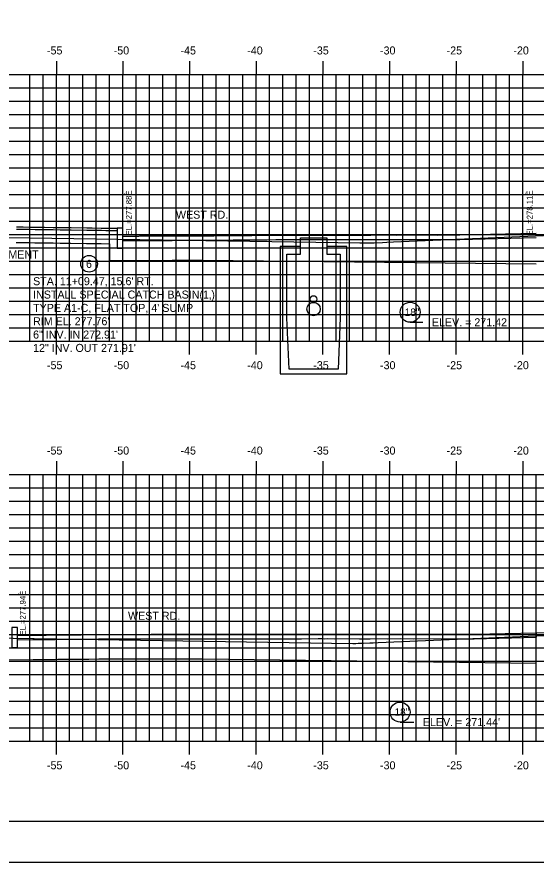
# Model space of a CAD drawing. Extents: x 853785 to 853955, y 366268 to 366378.
# Drawn here: x 853810.5 to 853849.4, y 366268.2 to 366331.6 of the extents above; entities that cross this region are included whole.
import ezdxf

# ---------------------------------------------------------------- set-up
doc = ezdxf.new("R2010")
doc.units = 0
for name, color, linetype in [('BORDER', 7, 'Continuous'), ('D_Curb_Type1_Lt', 7, 'Continuous'), ('D_Drainage_CB_TypeA1-B1', 7, 'Continuous'), ('D_Drainage_Culvert', 7, 'Continuous'), ('D_Drainage_Text', 7, 'Continuous'), ('D_Roadway_Edge_Shoulder', 7, 'Continuous'), ('D_Roadway_Sidewalks_Paved', 7, 'Continuous'), ('D_Roadway_SubGrade', 7, 'Continuous'), ('D_Text_Standard', 7, 'Continuous'), ('H_V ANNOTATION', 7, 'Continuous'), ('MAJOR', 7, 'Continuous'), ('MINOR', 7, 'Continuous'), ('PDRAIN', 7, 'Continuous'), ('PLOT BOUNDARY', 7, 'Continuous'), ('S_Roadway_Centerline', 7, 'Continuous')]:
    doc.layers.add(name, color=color, linetype=linetype)

msp = doc.modelspace()

# ---------------------------------------------------------------- linework, layer by layer
at = {"layer": 'BORDER'}
msp.add_line((853793.435, 366271.236), (853953.435, 366271.236), dxfattribs=at)
at = {"layer": 'D_Curb_Type1_Lt'}
for points in [[(853817.998, 366315.701), (853817.998, 366314.201), (853818.414, 366314.201), (853818.414, 366315.701)], [(853810.098, 366285.777), (853810.098, 366284.277), (853810.515, 366284.277), (853810.515, 366285.777)]]:
    msp.add_lwpolyline(points, close=True, dxfattribs=at)
at = {"layer": 'D_Drainage_CB_TypeA1-B1'}
for p, q in [((853830.734, 366314.331), (853830.242, 366314.331)), ((853830.242, 366314.331), (853830.242, 366304.786)), ((853831.751, 366314.331), (853830.734, 366314.331)), ((853834.737, 366314.331), (853833.72, 366314.331)), ((853835.229, 366314.331), (853834.737, 366314.331)), ((853835.229, 366304.786), (853835.229, 366314.331)), ((853830.734, 366308.984), (853830.734, 366312.33)), ((853834.737, 366312.33), (853834.737, 366308.984)), ((853830.898, 366305.146), (853830.734, 366308.984)), ((853834.737, 366308.984), (853834.573, 366305.146)), ((853834.573, 366305.146), (853830.898, 366305.146)), ((853830.242, 366304.786), (853835.229, 366304.786))]:
    msp.add_line(p, q, dxfattribs=at)
for points in [[(853831.226, 366314.373), (853831.751, 366314.373), (853831.751, 366314.996), (853833.72, 366314.996), (853833.72, 366314.373), (853834.244, 366314.373)], [(853830.734, 366312.33), (853830.734, 366313.754), (853831.751, 366313.754), (853831.751, 366314.331)], [(853833.72, 366314.331), (853833.72, 366313.754), (853834.737, 366313.754), (853834.737, 366312.33)]]:
    msp.add_lwpolyline(points, dxfattribs=at)
at = {"layer": 'D_Drainage_Culvert'}
for centre in [(853839.987, 366309.406), (853839.225, 366279.426)]:
    msp.add_circle(centre, 0.75, dxfattribs=at)
at = {"layer": 'D_Drainage_Text'}
msp.add_circle((853815.889, 366313.039), 0.625, dxfattribs=at)
at = {"layer": 'D_Roadway_Edge_Shoulder'}
msp.add_line((853849.435, 366285.374), (853849.439, 366285.041), dxfattribs=at)
for points in [[(853818.414, 366315.118), (853819.608, 366315.123), (853819.616, 366315.123), (853819.706, 366315.124), (853819.911, 366315.124), (853819.935, 366315.125), (853820.764, 366315.128), (853820.93, 366315.128), (853821.375, 366315.129), (853821.509, 366315.13), (853821.63, 366315.13), (853821.671, 366315.13), (853821.936, 366315.131), (853822.035, 366315.131), (853822.121, 366315.132), (853822.155, 366315.132), (853822.818, 366315.134), (853823.159, 366315.136), (853823.273, 366315.136), (853823.342, 366315.137), (853823.894, 366315.139), (853824.306, 366315.142), (853824.485, 366315.143), (853824.649, 366315.144), (853824.855, 366315.145), (853825.068, 366315.146), (853825.256, 366315.147), (853825.481, 366315.149), (853825.954, 366315.152), (853826.691, 366315.157), (853826.746, 366315.157), (853826.865, 366315.158), (853826.989, 366315.159), (853827.288, 366315.161), (853827.45, 366315.163), (853827.942, 366315.167), (853828.092, 366315.168), (853828.754, 366315.174), (853828.809, 366315.174), (853829.24, 366315.178), (853829.913, 366315.185), (853830.12, 366315.185), (853830.122, 366315.185), (853830.531, 366315.186), (853830.677, 366315.186), (853830.71, 366315.186), (853832.484, 366315.19), (853832.57, 366315.19), (853832.62, 366315.19), (853832.908, 366315.191), (853833.074, 366315.19), (853834.536, 366315.194), (853834.871, 366315.193), (853835.97, 366315.196), (853836.575, 366315.198), (853837.04, 366315.196), (853838.396, 366315.2), (853838.965, 366315.198), (853840.652, 366315.203), (853841.349, 366315.201), (853842.049, 366315.198), (853843.701, 366315.203), (853849.435, 366315.344)], [(853818.414, 366314.784), (853819.609, 366314.79), (853819.618, 366314.79), (853819.708, 366314.79), (853819.912, 366314.791), (853820.765, 366314.794), (853820.931, 366314.795), (853821.376, 366314.796), (853821.511, 366314.796), (853821.632, 366314.797), (853821.672, 366314.797), (853821.937, 366314.798), (853822.036, 366314.798), (853822.122, 366314.798), (853822.157, 366314.799), (853822.819, 366314.801), (853823.16, 366314.803), (853823.275, 366314.803), (853823.344, 366314.803), (853823.896, 366314.806), (853824.307, 366314.808), (853824.487, 366314.809), (853824.651, 366314.81), (853824.857, 366314.811), (853825.07, 366314.813), (853825.258, 366314.814), (853825.483, 366314.815), (853825.956, 366314.818), (853826.694, 366314.824), (853826.749, 366314.824), (853826.867, 366314.825), (853826.992, 366314.826), (853827.29, 366314.828), (853827.453, 366314.829), (853827.945, 366314.833), (853828.095, 366314.835), (853828.757, 366314.84), (853828.812, 366314.841), (853829.243, 366314.845), (853829.915, 366314.851), (853830.12, 366314.852), (853830.122, 366314.852), (853830.532, 366314.853), (853830.676, 366314.853), (853830.71, 366314.853), (853832.484, 366314.857), (853832.569, 366314.857), (853832.62, 366314.857), (853832.907, 366314.857), (853833.074, 366314.857), (853834.536, 366314.861), (853834.87, 366314.86), (853835.971, 366314.862), (853836.575, 366314.864), (853837.04, 366314.863), (853838.396, 366314.867), (853838.965, 366314.865), (853840.652, 366314.87), (853842.049, 366314.865), (853843.706, 366314.87), (853849.435, 366315.011)], [(853810.515, 366285.178), (853810.685, 366285.181), (853810.705, 366285.181), (853811.666, 366285.193), (853811.964, 366285.197), (853812.017, 366285.197), (853812.094, 366285.198), (853812.491, 366285.203), (853812.676, 366285.205), (853813.322, 366285.212), (853813.523, 366285.215), (853813.611, 366285.216), (853813.958, 366285.219), (853814.604, 366285.225), (853814.909, 366285.227), (853815.296, 366285.23), (853815.403, 366285.231), (853815.505, 366285.232), (853815.689, 366285.233), (853815.863, 366285.234), (853816.605, 366285.239), (853817.101, 366285.242), (853817.265, 366285.243), (853817.351, 366285.244), (853817.557, 366285.245), (853817.999, 366285.248), (853818.238, 366285.249), (853818.321, 366285.249), (853818.994, 366285.253), (853819.155, 366285.254), (853819.219, 366285.254), (853819.522, 366285.255), (853820.541, 366285.259), (853820.615, 366285.26), (853820.703, 366285.26), (853820.708, 366285.26), (853820.72, 366285.26), (853820.923, 366285.261), (853820.956, 366285.261), (853821.438, 366285.262), (853821.878, 366285.262), (853821.885, 366285.262), (853822.489, 366285.261), (853822.493, 366285.261), (853822.657, 366285.26), (853822.668, 366285.26), (853823.035, 366285.26), (853823.04, 366285.26), (853823.16, 366285.26), (853823.202, 366285.26), (853824.18, 366285.259), (853824.192, 366285.259), (853824.364, 366285.259), (853824.433, 366285.259), (853824.458, 366285.259), (853825.345, 366285.259), (853825.385, 366285.259), (853825.424, 366285.259), (853825.73, 366285.259), (853826.092, 366285.259), (853826.226, 366285.259), (853826.581, 366285.259), (853826.602, 366285.259), (853826.652, 366285.259), (853827.636, 366285.26), (853827.729, 366285.26), (853827.864, 366285.26), (853827.982, 366285.26), (853828.308, 366285.26), (853828.382, 366285.26), (853828.869, 366285.261), (853829.013, 366285.261), (853829.593, 366285.262), (853829.671, 366285.261), (853829.699, 366285.261), (853830.031, 366285.262), (853830.404, 366285.261), (853831.009, 366285.262), (853831.075, 366285.262), (853831.367, 366285.263), (853831.471, 366285.263), (853831.827, 366285.262), (853833.088, 366285.265), (853833.399, 366285.264), (853833.579, 366285.264), (853833.784, 366285.264), (853834.337, 366285.262), (853835.375, 366285.265), (853836.192, 366285.262), (853836.973, 366285.264), (853837.402, 366285.265), (853838.312, 366285.262), (853839.275, 366285.264), (853840.259, 366285.261), (853841.457, 366285.265), (853842.531, 366285.261), (853843.609, 366285.257), (853844.782, 366285.26), (853849.435, 366285.374)], [(853849.435, 366285.374), (853857.441, 366285.585), (853868.438, 366285.387), (853879.438, 366285.167), (853887.438, 366284.847)], [(853810.515, 366284.845), (853811.67, 366284.86), (853811.968, 366284.863), (853812.021, 366284.864), (853812.098, 366284.865), (853812.495, 366284.87), (853812.68, 366284.872), (853813.326, 366284.879), (853813.527, 366284.881), (853813.615, 366284.882), (853813.961, 366284.885), (853814.606, 366284.891), (853814.912, 366284.894), (853815.299, 366284.897), (853815.406, 366284.897), (853815.507, 366284.898), (853815.691, 366284.9), (853815.865, 366284.901), (853816.607, 366284.906), (853817.103, 366284.909), (853817.267, 366284.91), (853817.353, 366284.911), (853817.559, 366284.912), (853818.001, 366284.914), (853818.24, 366284.916), (853818.322, 366284.916), (853818.996, 366284.919), (853819.157, 366284.92), (853819.221, 366284.921), (853819.524, 366284.922), (853820.542, 366284.926), (853820.617, 366284.926), (853820.704, 366284.927), (853820.709, 366284.927), (853820.721, 366284.927), (853820.957, 366284.928), (853821.439, 366284.929), (853821.878, 366284.928), (853821.885, 366284.928), (853822.489, 366284.927), (853822.493, 366284.927), (853822.657, 366284.927), (853822.668, 366284.927), (853823.035, 366284.927), (853823.04, 366284.927), (853823.16, 366284.927), (853823.202, 366284.927), (853824.18, 366284.926), (853824.192, 366284.926), (853824.364, 366284.926), (853824.433, 366284.926), (853824.458, 366284.926), (853825.345, 366284.926), (853825.385, 366284.926), (853825.424, 366284.926), (853825.73, 366284.926), (853826.226, 366284.926), (853826.581, 366284.926), (853826.602, 366284.926), (853826.652, 366284.926), (853827.636, 366284.927), (853827.729, 366284.927), (853827.864, 366284.927), (853827.982, 366284.927), (853828.308, 366284.927), (853828.382, 366284.927), (853828.869, 366284.928), (853829.013, 366284.927), (853829.593, 366284.928), (853829.671, 366284.928), (853829.699, 366284.928), (853830.031, 366284.929), (853830.404, 366284.928), (853831.009, 366284.929), (853831.075, 366284.929), (853831.368, 366284.93), (853831.47, 366284.93), (853831.827, 366284.929), (853833.088, 366284.932), (853833.398, 366284.931), (853833.579, 366284.93), (853833.784, 366284.931), (853834.336, 366284.929), (853835.375, 366284.931), (853836.192, 366284.928), (853836.974, 366284.93), (853837.402, 366284.932), (853838.312, 366284.928), (853839.275, 366284.931), (853840.259, 366284.928), (853841.457, 366284.931), (853843.609, 366284.923), (853844.786, 366284.927), (853849.435, 366285.041)]]:
    msp.add_lwpolyline(points, dxfattribs=at)
at = {"layer": 'D_Roadway_Sidewalks_Paved'}
for points in [[(853810.447, 366315.806), (853810.67, 366315.803), (853810.953, 366315.799), (853811.403, 366315.793), (853811.839, 366315.787), (853811.975, 366315.786), (853812.147, 366315.783), (853812.559, 366315.777), (853813.204, 366315.768), (853813.733, 366315.76), (853813.943, 366315.757), (853814.001, 366315.756), (853814.165, 366315.754), (853814.256, 366315.752), (853814.546, 366315.748), (853815.713, 366315.731), (853815.866, 366315.729), (853815.893, 366315.729), (853816.132, 366315.725), (853816.803, 366315.716), (853816.822, 366315.715), (853817.152, 366315.711), (853817.998, 366315.704)], [(853810.444, 366315.639), (853810.667, 366315.636), (853810.951, 366315.632), (853811.401, 366315.626), (853811.836, 366315.621), (853811.972, 366315.619), (853812.145, 366315.617), (853812.557, 366315.611), (853813.202, 366315.601), (853813.731, 366315.593), (853813.94, 366315.59), (853813.998, 366315.59), (853814.162, 366315.587), (853814.254, 366315.586), (853814.544, 366315.581), (853815.711, 366315.564), (853815.863, 366315.562), (853815.89, 366315.562), (853816.129, 366315.558), (853816.801, 366315.549), (853816.82, 366315.549), (853817.15, 366315.544), (853817.997, 366315.538)]]:
    msp.add_lwpolyline(points, dxfattribs=at)
at = {"layer": 'D_Roadway_SubGrade'}
for p, q in [((853817.414, 366314.54), (853817.414, 366313.28)), ((853824.435, 366313.309), (853849.435, 366313.037)), ((853824.435, 366283.424), (853849.444, 366283.092))]:
    msp.add_line(p, q, dxfattribs=at)
for points in [[(853810.431, 366314.639), (853810.654, 366314.636), (853810.937, 366314.632), (853811.388, 366314.626), (853811.823, 366314.621), (853811.959, 366314.619), (853812.131, 366314.617), (853812.543, 366314.611), (853813.187, 366314.601), (853813.716, 366314.594), (853813.926, 366314.59), (853813.984, 366314.59), (853814.148, 366314.587), (853814.239, 366314.586), (853814.529, 366314.582), (853815.696, 366314.565), (853815.849, 366314.562), (853815.876, 366314.562), (853816.115, 366314.559), (853816.786, 366314.549), (853816.806, 366314.549), (853817.414, 366314.54)], [(853817.414, 366313.28), (853819.615, 366313.29), (853819.624, 366313.29), (853819.714, 366313.29), (853819.918, 366313.291), (853820.77, 366313.294), (853820.935, 366313.295), (853821.381, 366313.296), (853821.515, 366313.296), (853821.637, 366313.297), (853821.677, 366313.297), (853821.942, 366313.298), (853822.042, 366313.298), (853822.128, 366313.298), (853822.163, 366313.299), (853822.826, 366313.301), (853823.167, 366313.303), (853823.282, 366313.303), (853823.351, 366313.303), (853823.904, 366313.306), (853824.435, 366313.309)], [(853809.515, 366283.332), (853811.689, 366283.36), (853811.987, 366283.363), (853812.038, 366283.364), (853812.116, 366283.365), (853812.513, 366283.37), (853812.697, 366283.372), (853813.343, 366283.379), (853813.543, 366283.381), (853813.629, 366283.382), (853813.975, 366283.385), (853814.619, 366283.391), (853814.923, 366283.394), (853815.311, 366283.397), (853815.417, 366283.398), (853815.518, 366283.398), (853815.702, 366283.4), (853815.876, 366283.401), (853816.617, 366283.406), (853817.113, 366283.409), (853817.277, 366283.41), (853817.362, 366283.411), (853817.568, 366283.412), (853818.009, 366283.414), (853818.248, 366283.416), (853818.33, 366283.416), (853819.004, 366283.419), (853819.165, 366283.42), (853819.228, 366283.421), (853819.53, 366283.422), (853820.549, 366283.426), (853820.623, 366283.426), (853820.71, 366283.427), (853820.715, 366283.427), (853820.726, 366283.427), (853820.962, 366283.428), (853821.44, 366283.429), (853821.878, 366283.428), (853821.885, 366283.428), (853824.435, 366283.424)]]:
    msp.add_lwpolyline(points, dxfattribs=at)
at = {"layer": 'D_Text_Standard'}
for points in [[(853839.987, 366308.656), (853840.252, 366308.656), (853840.932, 366308.656)], [(853839.225, 366278.676), (853839.575, 366278.676), (853840.255, 366278.676)]]:
    msp.add_lwpolyline(points, dxfattribs=at)
at = {"layer": 'MAJOR'}
for p, q in [((853813.435, 366328.238), (853813.435, 366327.236)), ((853818.435, 366328.238), (853818.435, 366327.236)), ((853823.435, 366328.238), (853823.435, 366327.236)), ((853828.435, 366328.238), (853828.435, 366327.236)), ((853833.435, 366328.238), (853833.435, 366327.236)), ((853838.435, 366328.238), (853838.435, 366327.236)), ((853843.435, 366328.238), (853843.435, 366327.236)), ((853848.435, 366328.238), (853848.435, 366327.236)), ((853798.435, 366327.236), (853938.435, 366327.236)), ((853798.435, 366327.236), (853938.435, 366327.236)), ((853813.435, 366307.236), (853813.435, 366327.236)), ((853818.435, 366307.236), (853818.435, 366327.236)), ((853823.435, 366307.236), (853823.435, 366327.236)), ((853828.435, 366307.236), (853828.435, 366327.236)), ((853833.435, 366307.236), (853833.435, 366327.236)), ((853838.435, 366307.236), (853838.435, 366327.236)), ((853843.435, 366307.236), (853843.435, 366327.236)), ((853848.435, 366307.236), (853848.435, 366327.236)), ((853798.435, 366322.236), (853938.435, 366322.236)), ((853798.435, 366317.236), (853938.435, 366317.236)), ((853798.435, 366312.236), (853938.435, 366312.236)), ((853798.435, 366307.236), (853938.435, 366307.236)), ((853798.435, 366307.236), (853938.435, 366307.236)), ((853813.435, 366306.234), (853813.435, 366307.236)), ((853818.435, 366306.234), (853818.435, 366307.236)), ((853823.435, 366306.234), (853823.435, 366307.236)), ((853828.435, 366306.234), (853828.435, 366307.236)), ((853833.435, 366306.234), (853833.435, 366307.236)), ((853838.435, 366306.234), (853838.435, 366307.236)), ((853843.435, 366306.234), (853843.435, 366307.236)), ((853848.435, 366306.234), (853848.435, 366307.236)), ((853813.435, 366298.238), (853813.435, 366297.236)), ((853818.435, 366298.238), (853818.435, 366297.236)), ((853823.435, 366298.238), (853823.435, 366297.236)), ((853828.435, 366298.238), (853828.435, 366297.236)), ((853833.435, 366298.238), (853833.435, 366297.236)), ((853838.435, 366298.238), (853838.435, 366297.236)), ((853843.435, 366298.238), (853843.435, 366297.236)), ((853848.435, 366298.238), (853848.435, 366297.236)), ((853798.435, 366297.236), (853938.435, 366297.236)), ((853798.435, 366297.236), (853938.435, 366297.236)), ((853813.435, 366277.236), (853813.435, 366297.236)), ((853818.435, 366277.236), (853818.435, 366297.236)), ((853823.435, 366277.236), (853823.435, 366297.236)), ((853828.435, 366277.236), (853828.435, 366297.236)), ((853833.435, 366277.236), (853833.435, 366297.236)), ((853838.435, 366277.236), (853838.435, 366297.236)), ((853843.435, 366277.236), (853843.435, 366297.236)), ((853848.435, 366277.236), (853848.435, 366297.236)), ((853798.435, 366292.236), (853938.435, 366292.236)), ((853798.435, 366287.236), (853938.435, 366287.236)), ((853798.435, 366282.236), (853938.435, 366282.236)), ((853798.435, 366277.236), (853938.435, 366277.236)), ((853798.435, 366277.236), (853938.435, 366277.236)), ((853813.435, 366276.234), (853813.435, 366277.236)), ((853818.435, 366276.234), (853818.435, 366277.236)), ((853823.435, 366276.234), (853823.435, 366277.236)), ((853828.435, 366276.234), (853828.435, 366277.236)), ((853833.435, 366276.234), (853833.435, 366277.236)), ((853838.435, 366276.234), (853838.435, 366277.236)), ((853843.435, 366276.234), (853843.435, 366277.236)), ((853848.435, 366276.234), (853848.435, 366277.236))]:
    msp.add_line(p, q, dxfattribs=at)
at = {"layer": 'MINOR'}
for p, q in [((853811.435, 366307.236), (853811.435, 366327.236)), ((853812.435, 366307.236), (853812.435, 366327.236)), ((853814.435, 366307.236), (853814.435, 366327.236)), ((853815.435, 366307.236), (853815.435, 366327.236)), ((853816.435, 366307.236), (853816.435, 366327.236)), ((853817.435, 366307.236), (853817.435, 366327.236)), ((853819.435, 366307.236), (853819.435, 366327.236)), ((853820.435, 366307.236), (853820.435, 366327.236)), ((853821.435, 366307.236), (853821.435, 366327.236)), ((853822.435, 366307.236), (853822.435, 366327.236)), ((853824.435, 366307.236), (853824.435, 366327.236)), ((853825.435, 366307.236), (853825.435, 366327.236)), ((853826.435, 366307.236), (853826.435, 366327.236)), ((853827.435, 366307.236), (853827.435, 366327.236)), ((853829.435, 366307.236), (853829.435, 366327.236)), ((853830.435, 366307.236), (853830.435, 366327.236)), ((853831.435, 366307.236), (853831.435, 366327.236)), ((853832.435, 366307.236), (853832.435, 366327.236)), ((853834.435, 366307.236), (853834.435, 366327.236)), ((853835.435, 366307.236), (853835.435, 366327.236)), ((853836.435, 366307.236), (853836.435, 366327.236)), ((853837.435, 366307.236), (853837.435, 366327.236)), ((853839.435, 366307.236), (853839.435, 366327.236)), ((853840.435, 366307.236), (853840.435, 366327.236)), ((853841.435, 366307.236), (853841.435, 366327.236)), ((853842.435, 366307.236), (853842.435, 366327.236)), ((853844.435, 366307.236), (853844.435, 366327.236)), ((853845.435, 366307.236), (853845.435, 366327.236)), ((853846.435, 366307.236), (853846.435, 366327.236)), ((853847.435, 366307.236), (853847.435, 366327.236)), ((853798.435, 366326.236), (853938.435, 366326.236)), ((853798.435, 366325.236), (853938.435, 366325.236)), ((853798.435, 366324.236), (853938.435, 366324.236)), ((853798.435, 366323.236), (853938.435, 366323.236)), ((853798.435, 366321.236), (853938.435, 366321.236)), ((853798.435, 366320.236), (853938.435, 366320.236)), ((853798.435, 366319.236), (853938.435, 366319.236)), ((853798.435, 366318.236), (853938.435, 366318.236)), ((853798.435, 366316.236), (853938.435, 366316.236)), ((853798.435, 366315.236), (853938.435, 366315.236)), ((853798.435, 366314.236), (853938.435, 366314.236)), ((853798.435, 366313.236), (853938.435, 366313.236)), ((853798.435, 366311.236), (853938.435, 366311.236)), ((853798.435, 366310.236), (853938.435, 366310.236)), ((853798.435, 366309.236), (853938.435, 366309.236)), ((853798.435, 366308.236), (853938.435, 366308.236)), ((853811.435, 366277.236), (853811.435, 366297.236)), ((853812.435, 366277.236), (853812.435, 366297.236)), ((853814.435, 366277.236), (853814.435, 366297.236)), ((853815.435, 366277.236), (853815.435, 366297.236)), ((853816.435, 366277.236), (853816.435, 366297.236)), ((853817.435, 366277.236), (853817.435, 366297.236)), ((853819.435, 366277.236), (853819.435, 366297.236)), ((853820.435, 366277.236), (853820.435, 366297.236)), ((853821.435, 366277.236), (853821.435, 366297.236)), ((853822.435, 366277.236), (853822.435, 366297.236)), ((853824.435, 366277.236), (853824.435, 366297.236)), ((853825.435, 366277.236), (853825.435, 366297.236)), ((853826.435, 366277.236), (853826.435, 366297.236)), ((853827.435, 366277.236), (853827.435, 366297.236)), ((853829.435, 366277.236), (853829.435, 366297.236)), ((853830.435, 366277.236), (853830.435, 366297.236)), ((853831.435, 366277.236), (853831.435, 366297.236)), ((853832.435, 366277.236), (853832.435, 366297.236)), ((853834.435, 366277.236), (853834.435, 366297.236)), ((853835.435, 366277.236), (853835.435, 366297.236)), ((853836.435, 366277.236), (853836.435, 366297.236)), ((853837.435, 366277.236), (853837.435, 366297.236)), ((853839.435, 366277.236), (853839.435, 366297.236)), ((853840.435, 366277.236), (853840.435, 366297.236)), ((853841.435, 366277.236), (853841.435, 366297.236)), ((853842.435, 366277.236), (853842.435, 366297.236)), ((853844.435, 366277.236), (853844.435, 366297.236)), ((853845.435, 366277.236), (853845.435, 366297.236)), ((853846.435, 366277.236), (853846.435, 366297.236)), ((853847.435, 366277.236), (853847.435, 366297.236)), ((853849.435, 366277.236), (853849.435, 366297.236)), ((853798.435, 366296.236), (853938.435, 366296.236)), ((853798.435, 366295.236), (853938.435, 366295.236)), ((853798.435, 366294.236), (853938.435, 366294.236)), ((853798.435, 366293.236), (853938.435, 366293.236)), ((853798.435, 366291.236), (853938.435, 366291.236)), ((853798.435, 366290.236), (853938.435, 366290.236)), ((853798.435, 366289.236), (853938.435, 366289.236)), ((853798.435, 366288.236), (853938.435, 366288.236)), ((853798.435, 366286.236), (853938.435, 366286.236)), ((853798.435, 366285.236), (853938.435, 366285.236)), ((853798.435, 366284.236), (853938.435, 366284.236)), ((853798.435, 366283.236), (853938.435, 366283.236)), ((853798.435, 366281.236), (853938.435, 366281.236)), ((853798.435, 366280.236), (853938.435, 366280.236)), ((853798.435, 366279.236), (853938.435, 366279.236)), ((853798.435, 366278.236), (853938.435, 366278.236))]:
    msp.add_line(p, q, dxfattribs=at)
at = {"layer": 'PDRAIN'}
for centre, radius in [((853832.735, 366310.396), 0.25), ((853832.735, 366309.646), 0.5)]:
    msp.add_circle(centre, radius, dxfattribs=at)
at = {"layer": 'PLOT BOUNDARY'}
msp.add_lwpolyline([(853785.342, 366268.177), (853955.342, 366268.177), (853955.342, 366378.177), (853785.342, 366378.177)], close=True, dxfattribs=at)
at = {"layer": 'S_Roadway_Centerline'}
for points in [[(853798.435, 366315.282), (853799.685, 366315.246), (853800.429, 366315.235), (853800.818, 366315.153), (853800.872, 366315.14), (853801.238, 366315.142), (853801.368, 366315.141), (853801.394, 366315.141), (853801.412, 366315.141), (853801.451, 366315.14), (853801.515, 366315.139), (853836.201, 366314.604), (853836.517, 366314.604), (853836.755, 366314.606), (853837.277, 366314.616), (853837.92, 366314.644), (853838.245, 366314.661), (853838.725, 366314.689), (853855.908, 366315.417)], [(853798.435, 366285.189), (853798.901, 366285.188), (853802.515, 366285.135), (853802.975, 366285.124), (853803.233, 366285.116), (853803.9, 366285.094), (853804.261, 366285.082), (853808.581, 366284.997), (853835.676, 366284.58), (853835.913, 366284.58), (853836.093, 366284.581), (853836.485, 366284.59), (853836.97, 366284.61), (853837.215, 366284.623), (853837.576, 366284.644), (853850.621, 366285.197)]]:
    msp.add_lwpolyline(points, dxfattribs=at)

# ---------------------------------------------------------------- texts
at = {"layer": 'D_Drainage_Text'}
for s, p in [("STA. 11+09.47, 15.6' RT.", (853811.69, 366311.432)), ('INSTALL SPECIAL CATCH BASIN(1‚)', (853811.69, 366310.432)), ("TYPE A1-C, FLAT TOP, 4' SUMP", (853811.69, 366309.432)), ("RIM EL. 277.76'", (853811.69, 366308.432)), ('6" INV. IN 272.91\'', (853811.69, 366307.432)), ('12" INV. OUT 271.91\'', (853811.69, 366306.432))]:
    msp.add_text(s, height=0.6, dxfattribs=at).set_placement(p)
at = {"layer": 'D_Text_Standard'}
for s, p in [(' EL.=277.88È', (853819.091, 366315.007)), (' EL.=278.11È', (853849.166, 366315.007)), (' EL.=277.94È', (853811.134, 366284.999))]:
    msp.add_text(s, height=0.4335, rotation=90, dxfattribs=at).set_placement(p)
for s, p in [('WEST RD.', (853822.411, 366316.42)), ('REMOVE EXISTING PAVEMENT', (853800.027, 366313.436)), ('ELEV. = 271.42', (853841.612, 366308.356)), ('WEST RD.', (853818.812, 366286.346)), ("ELEV. = 271.44'", (853840.935, 366278.376))]:
    msp.add_text(s, height=0.6, dxfattribs=at).set_placement(p)
at = {"layer": 'H_V ANNOTATION'}
for s, p in [('-55', (853812.731, 366328.736)), ('-50', (853817.739, 366328.736)), ('-45', (853822.753, 366328.736)), ('-40', (853827.761, 366328.736)), ('-35', (853832.715, 366328.736)), ('-30', (853837.723, 366328.736)), ('-25', (853842.721, 366328.736)), ('-20', (853847.729, 366328.736)), ('6', (853815.659, 366312.734)), ('-55', (853812.731, 366305.136)), ('-50', (853817.739, 366305.136)), ('-45', (853822.753, 366305.136)), ('-40', (853827.761, 366305.136)), ('-35', (853832.715, 366305.136)), ('-30', (853837.723, 366305.136)), ('-25', (853842.721, 366305.136)), ('-20', (853847.729, 366305.136)), ('-55', (853812.731, 366298.736)), ('-50', (853817.739, 366298.736)), ('-45', (853822.753, 366298.736)), ('-40', (853827.761, 366298.736)), ('-35', (853832.715, 366298.736)), ('-30', (853837.723, 366298.736)), ('-25', (853842.721, 366298.736)), ('-20', (853847.729, 366298.736)), ('-55', (853812.731, 366275.136)), ('-50', (853817.739, 366275.136)), ('-45', (853822.753, 366275.136)), ('-40', (853827.761, 366275.136)), ('-35', (853832.715, 366275.136)), ('-30', (853837.723, 366275.136)), ('-25', (853842.721, 366275.136)), ('-20', (853847.729, 366275.136))]:
    msp.add_text(s, height=0.6, dxfattribs=at).set_placement(p)
at = {"layer": 'PDRAIN'}
for p in [(853839.576, 366309.125), (853838.814, 366279.145)]:
    msp.add_text('18"', height=0.5625, dxfattribs=at).set_placement(p)

doc.saveas('drawing.dxf')
